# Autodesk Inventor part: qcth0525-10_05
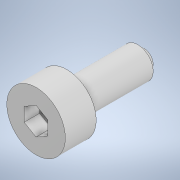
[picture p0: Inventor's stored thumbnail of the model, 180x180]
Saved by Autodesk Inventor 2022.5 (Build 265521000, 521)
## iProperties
Created: 2022-02
Part Number: qcth0525-10_05
Material: 一般
Document SubType Name: Modeling
Designer: ImaoCorp
Density: 1 g/cm^3
Appearance: 既定
Author: ImaoCorp
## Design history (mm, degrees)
feature "qcth0525-10_05"
node "ソリッド1"
